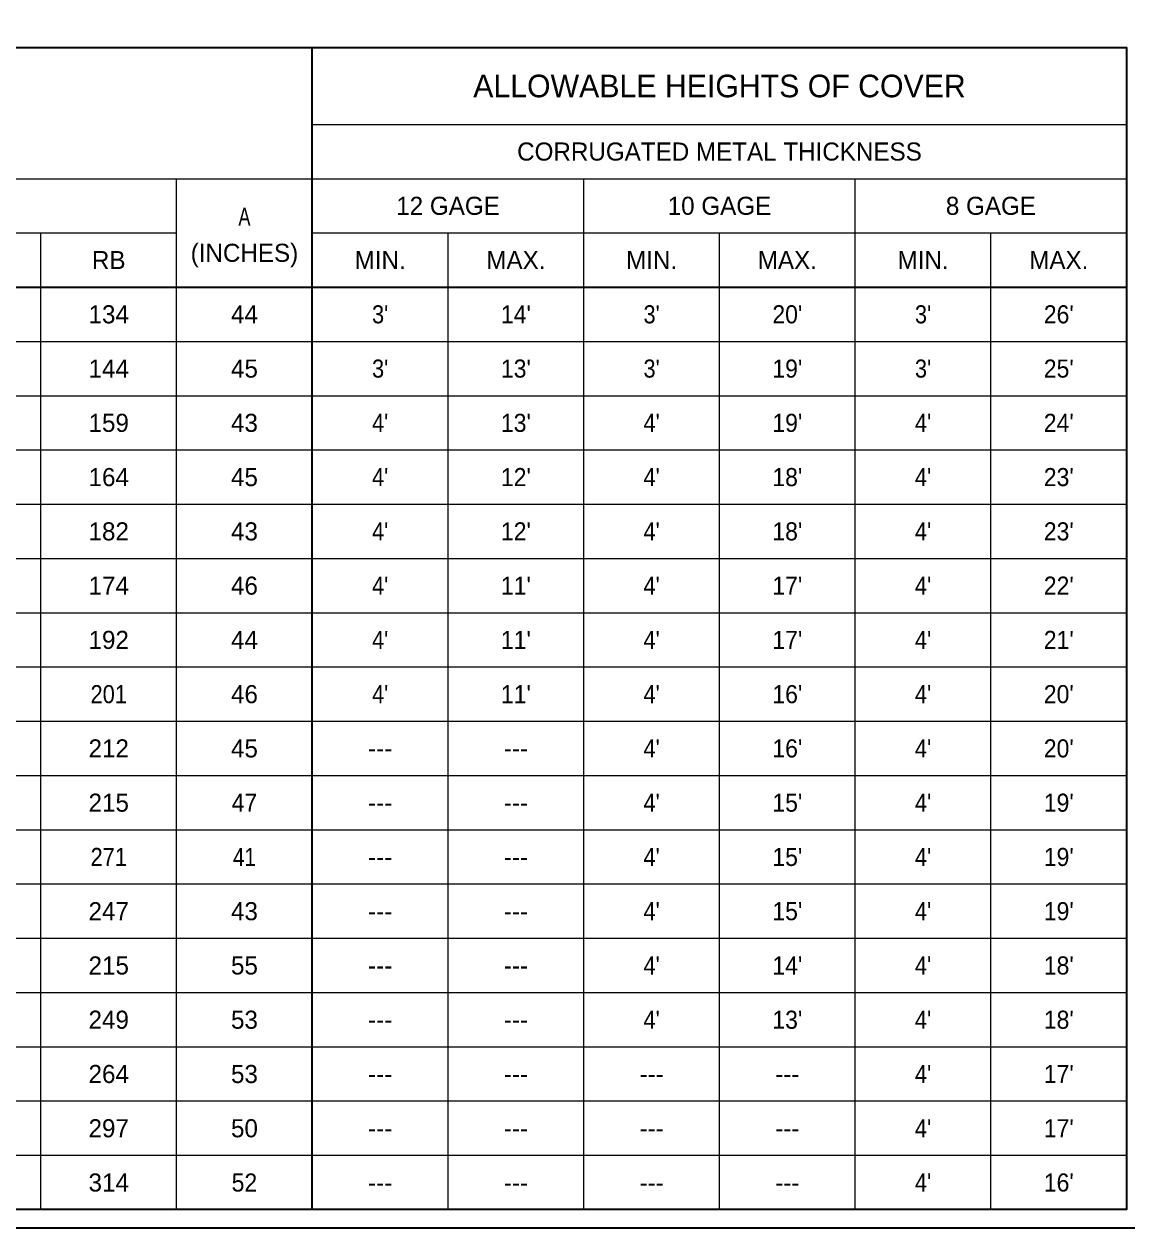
# Model space of a CAD drawing. Extents: x 99860 to 103153, y 99998 to 102077.
# Drawn here: x 101073 to 102048, y 100000 to 101064 of the extents above; entities that cross this region are included whole.
import ezdxf
from ezdxf.enums import TextEntityAlignment as Align

# ---------------------------------------------------------------- set-up
doc = ezdxf.new("R2010")
doc.units = 0
doc.header["$LTSCALE"] = 6.4
for name, color, linetype, lineweight in [('1', 7, 'Continuous', 35), ('20', 7, 'Continuous', 13), ('40', 7, 'Continuous', 35)]:
    doc.layers.add(name, color=color, linetype=linetype, lineweight=lineweight)

msp = doc.modelspace()

# ---------------------------------------------------------------- linework, layer by layer
at = {"layer": '1'}
msp.add_lwpolyline([(99862, 99999.5), (103151, 99999.5), (103151, 102075.5), (99862, 102075.5)], close=True, dxfattribs=at)
at = {"layer": '40'}
for p, q in [((101327.715, 100879.654), (101327.715, 101043.644)), ((101327.715, 100831.674), (101327.715, 100975.644)), ((100007.715, 100831.674), (102047.715, 100831.674)), ((101327.715, 100015.804), (101327.715, 100831.674))]:
    msp.add_line(p, q, dxfattribs=at)
at = {"layer": '40', "lineweight": 25}
for p, q in [((101327.715, 100975.654), (102047.715, 100975.654)), ((100007.715, 100927.654), (101327.715, 100927.654)), ((101207.715, 100015.804), (101207.715, 100927.654)), ((101327.715, 100927.644), (102047.715, 100927.644)), ((101567.715, 100015.804), (101567.715, 100927.654)), ((101807.715, 100015.804), (101807.715, 100927.654))]:
    msp.add_line(p, q, dxfattribs=at)
at = {"layer": '40', "lineweight": 13}
for p, q in [((100247.715, 100879.664), (101207.715, 100879.664)), ((101087.715, 100015.804), (101087.715, 100879.664)), ((101327.715, 100879.654), (102047.715, 100879.654)), ((101447.715, 100015.804), (101447.715, 100879.654)), ((101687.715, 100015.804), (101687.715, 100879.654)), ((101927.715, 100015.804), (101927.715, 100879.664)), ((100007.715, 100783.684), (102047.715, 100783.684)), ((100007.715, 100735.684), (102047.715, 100735.684)), ((100007.715, 100687.694), (102047.715, 100687.694)), ((100007.715, 100639.704), (102047.715, 100639.704)), ((100007.715, 100591.714), (102047.715, 100591.714)), ((100007.715, 100543.724), (102047.715, 100543.724)), ((100007.715, 100495.724), (102047.715, 100495.724)), ((100007.715, 100447.734), (102047.715, 100447.734)), ((100007.715, 100399.744), (102047.715, 100399.744)), ((100007.715, 100351.754), (102047.715, 100351.754)), ((100007.715, 100303.764), (102047.715, 100303.764)), ((100007.715, 100255.764), (102047.715, 100255.764)), ((100007.715, 100207.774), (102047.715, 100207.774)), ((100007.715, 100159.784), (102047.715, 100159.784)), ((100007.715, 100111.794), (102047.715, 100111.794)), ((100007.715, 100063.804), (102047.715, 100063.804))]:
    msp.add_line(p, q, dxfattribs=at)
at = {"layer": '40'}
msp.add_lwpolyline([(100007.715, 101043.644), (102047.715, 101043.644), (102047.715, 100015.804), (100007.715, 100015.804)], close=True, dxfattribs=at)

# ---------------------------------------------------------------- texts
at = {"layer": '20'}
for s, height, p in [('ALLOWABLE HEIGHTS OF COVER', 20, (101687.717, 100999.649)), ('CORRUGATED METAL THICKNESS', 16, (101687.715, 100943.649)), ('12 GAGE', 16, (101447.715, 100895.654)), ('10 GAGE', 16, (101687.715, 100895.659)), ('8 GAGE', 16, (101927.715, 100895.654)), ('(INCHES)', 16, (101267.715, 100854.079)), ('RB', 16, (101147.716, 100847.669)), ('MIN.', 16, (101387.716, 100847.664)), ('MAX.', 16, (101507.717, 100847.669)), ('MIN.', 16, (101627.717, 100847.669)), ('MAX.', 16, (101747.717, 100847.669)), ('MIN.', 16, (101867.717, 100847.669)), ('MAX.', 16, (101987.717, 100847.664)), ('134', 16, (101147.717, 100799.674)), ('44', 16, (101267.716, 100799.674)), ('144', 16, (101147.717, 100751.674)), ('45', 16, (101267.716, 100751.674)), ('159', 16, (101147.717, 100703.674)), ('43', 16, (101267.716, 100703.674)), ('164', 16, (101147.717, 100655.674)), ('45', 16, (101267.716, 100655.674)), ('182', 16, (101147.716, 100607.674)), ('43', 16, (101267.716, 100607.674)), ('174', 16, (101147.717, 100559.674)), ('46', 16, (101267.716, 100559.674)), ('192', 16, (101147.716, 100511.674)), ('44', 16, (101267.716, 100511.674)), ('46', 16, (101267.716, 100463.674)), ('212', 16, (101147.716, 100415.674)), ('45', 16, (101267.716, 100415.674)), ('---', 16, (101387.716, 100415.674)), ('---', 16, (101507.716, 100415.674)), ('215', 16, (101147.717, 100367.674)), ('---', 16, (101387.716, 100367.674)), ('---', 16, (101507.716, 100367.674)), ('---', 16, (101387.716, 100319.674)), ('---', 16, (101507.716, 100319.674)), ('247', 16, (101147.716, 100271.674)), ('43', 16, (101267.716, 100271.674)), ('---', 16, (101387.716, 100271.674)), ('---', 16, (101507.716, 100271.674)), ('215', 16, (101147.717, 100223.674)), ('55', 16, (101267.716, 100223.674)), ('---', 16, (101387.716, 100223.674)), ('---', 16, (101507.716, 100223.674)), ('249', 16, (101147.717, 100175.674)), ('53', 16, (101267.716, 100175.674)), ('---', 16, (101387.716, 100175.674)), ('---', 16, (101507.716, 100175.674)), ('264', 16, (101147.717, 100127.674)), ('53', 16, (101267.716, 100127.674)), ('---', 16, (101387.716, 100127.674)), ('---', 16, (101507.716, 100127.674)), ('---', 16, (101627.716, 100127.674)), ('---', 16, (101747.716, 100127.674)), ('297', 16, (101147.716, 100079.674)), ('50', 16, (101267.716, 100079.674)), ('---', 16, (101387.716, 100079.674)), ('---', 16, (101507.716, 100079.674)), ('---', 16, (101627.716, 100079.674)), ('---', 16, (101747.716, 100079.674)), ('314', 16, (101147.717, 100031.674)), ('---', 16, (101387.716, 100031.674)), ('---', 16, (101507.716, 100031.674)), ('---', 16, (101627.716, 100031.674)), ('---', 16, (101747.716, 100031.674))]:
    msp.add_text(s, height=height, dxfattribs=at).set_placement(p, align=Align.CENTER)
for s, width, p in [('A', 0.75, (101267.716, 100886.079)), ("3'", 0.9, (101387.717, 100799.674)), ("14'", 0.95, (101507.717, 100799.674)), ("3'", 0.9, (101627.717, 100799.674)), ("20'", 0.95, (101747.717, 100799.674)), ("3'", 0.9, (101867.717, 100799.674)), ("26'", 0.95, (101987.717, 100799.674)), ("3'", 0.9, (101387.717, 100751.674)), ("13'", 0.95, (101507.717, 100751.674)), ("3'", 0.9, (101627.717, 100751.674)), ("19'", 0.95, (101747.717, 100751.674)), ("3'", 0.9, (101867.717, 100751.674)), ("25'", 0.95, (101987.717, 100751.674)), ("4'", 0.9, (101387.717, 100703.674)), ("13'", 0.95, (101507.717, 100703.674)), ("4'", 0.9, (101627.717, 100703.674)), ("19'", 0.95, (101747.717, 100703.674)), ("4'", 0.9, (101867.717, 100703.674)), ("24'", 0.95, (101987.717, 100703.674)), ("4'", 0.9, (101387.717, 100655.674)), ("12'", 0.95, (101507.717, 100655.674)), ("4'", 0.9, (101627.717, 100655.674)), ("18'", 0.95, (101747.717, 100655.674)), ("4'", 0.9, (101867.717, 100655.674)), ("23'", 0.95, (101987.717, 100655.674)), ("4'", 0.9, (101387.717, 100607.674)), ("12'", 0.95, (101507.717, 100607.674)), ("4'", 0.9, (101627.717, 100607.674)), ("18'", 0.95, (101747.717, 100607.674)), ("4'", 0.9, (101867.717, 100607.674)), ("23'", 0.95, (101987.717, 100607.674)), ("4'", 0.9, (101387.717, 100559.674)), ("11'", 0.95, (101507.717, 100559.674)), ("4'", 0.9, (101627.717, 100559.674)), ("17'", 0.95, (101747.717, 100559.674)), ("4'", 0.9, (101867.717, 100559.674)), ("22'", 0.95, (101987.717, 100559.674)), ("4'", 0.9, (101387.717, 100511.674)), ("11'", 0.95, (101507.717, 100511.674)), ("4'", 0.9, (101627.717, 100511.674)), ("17'", 0.95, (101747.717, 100511.674)), ("4'", 0.9, (101867.717, 100511.674)), ("21'", 0.95, (101987.717, 100511.674)), ('201', 0.9, (101147.717, 100463.674)), ("4'", 0.9, (101387.717, 100463.674)), ("11'", 0.95, (101507.717, 100463.674)), ("4'", 0.9, (101627.717, 100463.674)), ("16'", 0.95, (101747.717, 100463.674)), ("4'", 0.9, (101867.717, 100463.674)), ("20'", 0.95, (101987.717, 100463.674)), ("4'", 0.9, (101627.717, 100415.674)), ("16'", 0.95, (101747.717, 100415.674)), ("4'", 0.9, (101867.717, 100415.674)), ("20'", 0.95, (101987.717, 100415.674)), ('47', 0.95, (101267.715, 100367.674)), ("4'", 0.9, (101627.717, 100367.674)), ("15'", 0.95, (101747.717, 100367.674)), ("4'", 0.9, (101867.717, 100367.674)), ("19'", 0.95, (101987.717, 100367.674)), ('271', 0.9, (101147.717, 100319.674)), ('41', 0.85, (101267.717, 100319.674)), ("4'", 0.9, (101627.717, 100319.674)), ("15'", 0.95, (101747.717, 100319.674)), ("4'", 0.9, (101867.717, 100319.674)), ("19'", 0.95, (101987.717, 100319.674)), ("4'", 0.9, (101627.717, 100271.674)), ("15'", 0.95, (101747.717, 100271.674)), ("4'", 0.9, (101867.717, 100271.674)), ("19'", 0.95, (101987.717, 100271.674)), ("4'", 0.9, (101627.717, 100223.674)), ("14'", 0.95, (101747.717, 100223.674)), ("4'", 0.9, (101867.717, 100223.674)), ("18'", 0.95, (101987.717, 100223.674)), ("4'", 0.9, (101627.717, 100175.674)), ("13'", 0.95, (101747.717, 100175.674)), ("4'", 0.9, (101867.717, 100175.674)), ("18'", 0.95, (101987.717, 100175.674)), ("4'", 0.9, (101867.717, 100127.674)), ("17'", 0.95, (101987.717, 100127.674)), ("4'", 0.9, (101867.717, 100079.674)), ("17'", 0.95, (101987.717, 100079.674)), ('52', 0.95, (101267.715, 100031.674)), ("16'", 0.95, (101987.717, 100031.674)), ("4'", 0.9, (101867.717, 100031.674))]:
    msp.add_text(s, height=16, dxfattribs=dict(at, width=width)).set_placement(p, align=Align.CENTER)

doc.saveas('drawing.dxf')
